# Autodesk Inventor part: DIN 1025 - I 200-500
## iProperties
IsCustomPart: 1
Created: 2007-02
Part Number: DIN 1025 - I 200-500
Material: Stahl, weich, unlegiert
Description: Warmgewalzte I-Träger
Document SubType Name: Modeling
Standard: DIN 1025
Designer: thomas
Standards Organization: DIN
Language: de-DE
Size Designation: I 200-500
Categories: <MemberInstance><Categories><Category DisplayName="Profilstähle" InternalName="089c4875-fa83-4c05-b084-43b9cc11f5ed" Mnemonic="GRDR"><CategoryParameter DisplayN
Stock Number: I 200
Density: 7.86 g/cm^3
G_L: 500,000 mm
Author: thomas
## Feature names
1. Extrusion1
